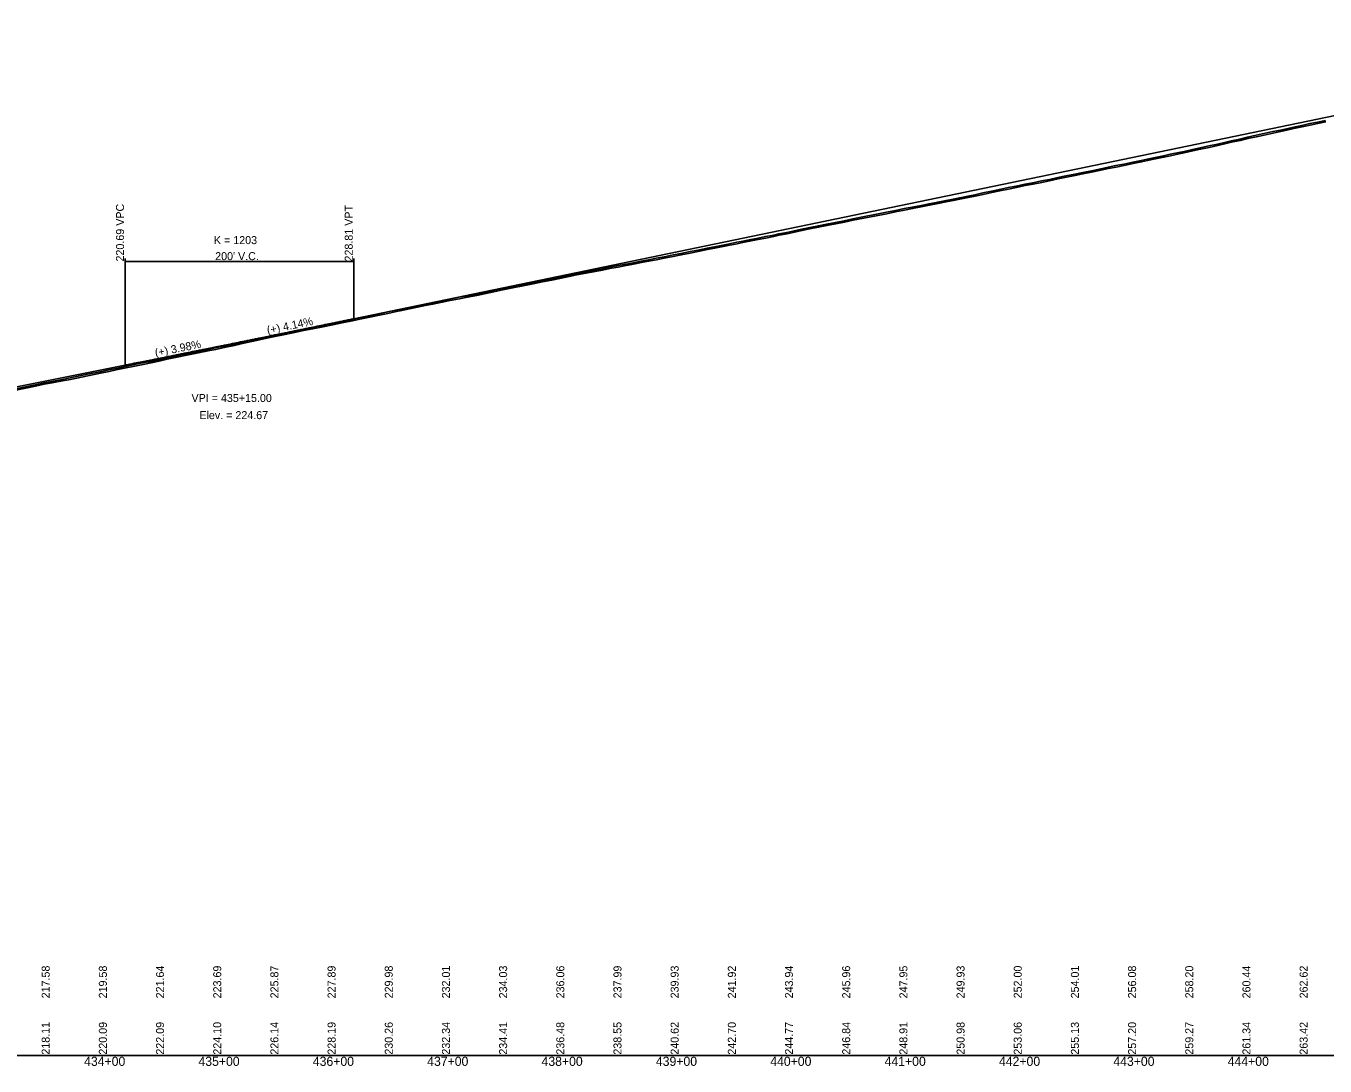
# Model space of a CAD drawing. Extents: x 1876258 to 1932803, y 754739 to 837911.
# Drawn here: x 1921691 to 1922827, y 827954 to 828863 of the extents above; entities that cross this region are included whole.
import ezdxf

# ---------------------------------------------------------------- set-up
doc = ezdxf.new("R2010")
doc.units = 0
for name, color, linetype in [('RD_DDB_GradeTX', 7, 'Continuous'), ('RD_DDB_Profile_EX', 7, 'Continuous'), ('RD_DDB_Profile_Lbl', 7, 'Continuous'), ('RD_DDB_Profile_PR', 7, 'Continuous'), ('RD_DDB_StaTX', 7, 'Continuous'), ('RD_DDB_StripGrade', 7, 'Continuous'), ('RD_DDB_VCLbl', 7, 'Continuous'), ('RD_GPK_Profile_Cell', 7, 'Continuous'), ('RD_Sketch1', 7, 'Continuous')]:
    doc.layers.add(name, color=color, linetype=linetype)

msp = doc.modelspace()

# ---------------------------------------------------------------- linework, layer by layer
at = {"layer": 'RD_DDB_GradeTX'}
for p in [(1921956.4, 828602.4), (1921799.6, 828570.5)]:
    msp.add_line(p, (1921878.1, 828586.1), dxfattribs=at)
at = {"layer": 'RD_DDB_Profile_EX'}
for points in [[(1922741, 828760.1), (1922745.5, 828761.1), (1922753, 828762.7), (1922759.9, 828764.3), (1922767.3, 828766), (1922774.2, 828767.4), (1922782, 828769.1), (1922787.1, 828770.2), (1922793.8, 828771.7), (1922799.9, 828773.1), (1922807.2, 828774.6), (1922814.3, 828776.2), (1922820.9, 828777.6), (1922828, 828779.1)], [(1921993.6, 828608.6), (1922000.5, 828609.9), (1922007.9, 828611.6), (1922015.3, 828613.2), (1922018.5, 828613.8), (1922026.8, 828615.5), (1922033.7, 828616.9), (1922042, 828618.6), (1922047.2, 828619.7), (1922055.4, 828621.3), (1922062.3, 828622.7), (1922070.5, 828624.3), (1922077.4, 828625.7), (1922085.6, 828627.3), (1922092.2, 828628.6), (1922100.4, 828630.3), (1922108.3, 828632), (1922134.8, 828637.4), (1922143, 828639.1), (1922151.2, 828640.7), (1922158.1, 828642.1), (1922166.3, 828643.8), (1922173.2, 828645.2), (1922181.3, 828646.7), (1922187.4, 828647.8), (1922194, 828649.1), (1922198.1, 828649.9), (1922203.4, 828651), (1922209.3, 828652), (1922214.6, 828653), (1922222.5, 828654.5), (1922229.6, 828655.9), (1922237.5, 828657.5), (1922242.6, 828658.5), (1922249.5, 828659.9), (1922257.4, 828661.4), (1922264.4, 828662.7), (1922272.3, 828664.3), (1922279.3, 828665.7), (1922287.2, 828667.3), (1922295.1, 828668.9), (1922305.4, 828670.9), (1922313.3, 828672.4), (1922316.9, 828673.2), (1922324.1, 828674.6), (1922331.7, 828676.1), (1922338.4, 828677.4), (1922345.4, 828678.8), (1922350.1, 828679.8), (1922356.9, 828681.2), (1922362.2, 828682.3), (1922369.9, 828683.9), (1922376.9, 828685.4), (1922384.5, 828686.8), (1922391.8, 828688.3), (1922399.4, 828689.8), (1922407, 828691.4), (1922414.6, 828692.9), (1922444, 828698.7), (1922451.8, 828700.3), (1922459.6, 828701.8), (1922466.6, 828703.2), (1922474.3, 828704.8), (1922481.3, 828706.1), (1922489, 828707.7), (1922496.1, 828709.1), (1922502.5, 828710.3), (1922508.1, 828711.4), (1922513.8, 828712.6), (1922521.3, 828714.1), (1922528.3, 828715.6), (1922536, 828717.2), (1922542.9, 828718.6), (1922550.5, 828720.2), (1922557.4, 828721.7), (1922565, 828723.2), (1922572, 828724.6), (1922579.6, 828726.1), (1922586.5, 828727.5), (1922594.1, 828729.1), (1922601.1, 828730.5), (1922608.7, 828732), (1922615.6, 828733.4), (1922623.2, 828735), (1922630.2, 828736.5), (1922638, 828738.1), (1922644.8, 828739.4), (1922651.7, 828740.9), (1922659.5, 828742.5), (1922666.9, 828744), (1922672.1, 828745.1), (1922679, 828746.6), (1922686.4, 828748.1), (1922692.3, 828749.3), (1922699.8, 828751), (1922704.2, 828751.9), (1922711.7, 828753.5), (1922718.5, 828755), (1922726, 828756.7), (1922733.5, 828758.4), (1922741, 828760.1)], [(1921679.9, 828543.9), (1921699.8, 828548), (1921707.4, 828549.6), (1921714.2, 828550.9), (1921723.2, 828552.6), (1921730.3, 828553.9), (1921740, 828555.9), (1921746.9, 828557.4), (1921756.4, 828559.4), (1921764.1, 828560.9), (1921770.3, 828562.2), (1921793.7, 828567), (1921800.7, 828568.3), (1921807.8, 828569.9), (1921814.9, 828571.4), (1921840.7, 828576.7), (1921847.9, 828578.1), (1921852.1, 828579), (1921857.4, 828580.1), (1921864.7, 828581.6), (1921873.6, 828583.5), (1921882, 828585.4), (1921890.3, 828587.3), (1921899.4, 828589.3), (1921907.6, 828591), (1921916.6, 828592.9), (1921925, 828594.6), (1921934, 828596.5), (1921942.3, 828598.1), (1921951.3, 828599.9), (1921959.6, 828601.5), (1921968, 828603.3), (1921976.9, 828605.1), (1921984.8, 828606.7), (1921993.6, 828608.6)]]:
    msp.add_lwpolyline(points, dxfattribs=at)
at = {"layer": 'RD_DDB_Profile_PR'}
for p, q in [((1921978.1, 828606.9), (1923213.1, 828862.8)), ((1921449.1, 828500.8), (1921778.1, 828566.3))]:
    msp.add_line(p, q, dxfattribs=at)
msp.add_spline([(1921778.1, 828566.3), (1921782.1, 828567.1), (1921786.1, 828567.9), (1921790.1, 828568.7), (1921794.1, 828569.4), (1921798.1, 828570.2), (1921802.1, 828571), (1921806.1, 828571.8), (1921810.1, 828572.6), (1921814.1, 828573.4), (1921818.1, 828574.2), (1921822.1, 828575.1), (1921826.1, 828575.9), (1921830.1, 828576.7), (1921834.1, 828577.5), (1921838.1, 828578.3), (1921842.1, 828579.1), (1921846.1, 828579.9), (1921850.1, 828580.7), (1921854.1, 828581.5), (1921858.1, 828582.3), (1921862.1, 828583.1), (1921866.1, 828583.9), (1921870.1, 828584.7), (1921874.1, 828585.5), (1921878.1, 828586.4), (1921882.1, 828587.2), (1921886.1, 828588), (1921890.1, 828588.8), (1921894.1, 828589.6), (1921898.1, 828590.4), (1921902.1, 828591.2), (1921906.1, 828592.1), (1921910.1, 828592.9), (1921914.1, 828593.7), (1921918.1, 828594.5), (1921922.1, 828595.3), (1921926.1, 828596.2), (1921930.1, 828597), (1921934.1, 828597.8), (1921938.1, 828598.6), (1921942.1, 828599.4), (1921946.1, 828600.3), (1921950.1, 828601.1), (1921954.1, 828601.9), (1921958.1, 828602.7), (1921962.1, 828603.6), (1921966.1, 828604.4), (1921970.1, 828605.2), (1921974.1, 828606), (1921978.1, 828606.9)], degree=3, dxfattribs=at)
at = {"layer": 'RD_DDB_VCLbl'}
for p, q in [((1921778.1, 828659.4), (1921778.1, 828566.3)), ((1921778.1, 828656.9), (1921978.1, 828656.9)), ((1921978.1, 828659.4), (1921978.1, 828606.9))]:
    msp.add_line(p, q, dxfattribs=at)
at = {"layer": 'RD_GPK_Profile_Cell'}
msp.add_line((1878363.1, 827962.8), (1926563.1, 827962.8), dxfattribs=at)
at = {"layer": 'RD_Sketch1'}
msp.add_lwpolyline([(1921679.6, 828545.1), (1921699.5, 828549.2), (1921707.2, 828550.8), (1921714, 828552.1), (1921722.9, 828553.8), (1921730, 828555.2), (1921739.7, 828557.2), (1921746.6, 828558.6), (1921756.2, 828560.6), (1921763.8, 828562.1), (1921770.1, 828563.4), (1921793.4, 828568.2), (1921800.5, 828569.6), (1921807.5, 828571.1), (1921814.6, 828572.6), (1921840.4, 828577.9), (1921847.6, 828579.4), (1921851.9, 828580.3), (1921857.1, 828581.4), (1921864.4, 828582.8), (1921873.3, 828584.7), (1921881.7, 828586.6), (1921890, 828588.5), (1921899.1, 828590.5), (1921907.4, 828592.3), (1921916.4, 828594.1), (1921924.7, 828595.8), (1921933.7, 828597.7), (1921942, 828599.3), (1921951, 828601.1), (1921959.3, 828602.8), (1921967.8, 828604.5), (1921976.6, 828606.3), (1921984.6, 828607.9), (1921993.4, 828609.8), (1922000.2, 828611.2), (1922007.7, 828612.8), (1922015, 828614.4), (1922018.2, 828615), (1922026.6, 828616.7), (1922033.5, 828618.1), (1922041.7, 828619.8), (1922046.9, 828620.9), (1922055.1, 828622.5), (1922062, 828623.9), (1922070.2, 828625.6), (1922077.1, 828626.9), (1922085.3, 828628.5), (1922092, 828629.9), (1922100.1, 828631.5), (1922108.1, 828633.2), (1922134.5, 828638.6), (1922142.8, 828640.3), (1922150.9, 828641.9), (1922157.8, 828643.3), (1922166, 828645), (1922173, 828646.4), (1922181.1, 828648), (1922187.2, 828649.1), (1922193.8, 828650.3), (1922197.9, 828651.1), (1922203.2, 828652.2), (1922209.1, 828653.3), (1922214.4, 828654.3), (1922222.2, 828655.7), (1922229.4, 828657.2), (1922237.3, 828658.8), (1922242.4, 828659.8), (1922249.3, 828661.1), (1922257.2, 828662.6), (1922264.1, 828663.9), (1922272.1, 828665.6), (1922279, 828666.9), (1922286.9, 828668.5), (1922294.9, 828670.1), (1922305.2, 828672.2), (1922313, 828673.7), (1922316.7, 828674.4), (1922323.8, 828675.8), (1922331.5, 828677.4), (1922338.1, 828678.7), (1922345.2, 828680), (1922349.8, 828681), (1922356.6, 828682.4), (1922362, 828683.5), (1922369.6, 828685.2), (1922376.7, 828686.6), (1922384.3, 828688.1), (1922391.5, 828689.5), (1922399.2, 828691.1), (1922406.8, 828692.6), (1922414.4, 828694.1), (1922443.7, 828699.9), (1922451.6, 828701.5), (1922459.4, 828703.1), (1922466.3, 828704.5), (1922474.1, 828706), (1922481.1, 828707.4), (1922488.7, 828708.9), (1922495.9, 828710.3), (1922502.2, 828711.5), (1922507.9, 828712.7), (1922513.5, 828713.8), (1922521, 828715.3), (1922528, 828716.8), (1922535.7, 828718.4), (1922542.6, 828719.9), (1922550.3, 828721.5), (1922557.2, 828722.9), (1922564.8, 828724.4), (1922571.7, 828725.8), (1922579.4, 828727.3), (1922586.3, 828728.7), (1922593.8, 828730.3), (1922600.8, 828731.7), (1922608.4, 828733.2), (1922615.4, 828734.6), (1922623, 828736.2), (1922630, 828737.7), (1922637.7, 828739.3), (1922644.5, 828740.7), (1922651.4, 828742.1), (1922659.2, 828743.7), (1922666.6, 828745.2), (1922671.8, 828746.3), (1922678.8, 828747.8), (1922686.2, 828749.4), (1922692, 828750.6), (1922699.6, 828752.2), (1922704, 828753.1), (1922711.4, 828754.7), (1922718.2, 828756.2), (1922725.7, 828758), (1922733.2, 828759.6), (1922740.7, 828761.3), (1922745.2, 828762.3), (1922752.7, 828763.9), (1922759.6, 828765.5), (1922767.1, 828767.2), (1922773.9, 828768.7), (1922781.8, 828770.4), (1922786.9, 828771.5), (1922793.5, 828772.9), (1922799.6, 828774.3), (1922806.9, 828775.9), (1922814.1, 828777.4), (1922820.7, 828778.8), (1922827.7, 828780.3)], dxfattribs=at)

# ---------------------------------------------------------------- texts
at = {"layer": 'RD_DDB_GradeTX'}
for s, rotation, p in [('(+) 4.14%', 11.7064, (1921902.8, 828593.3)), ('(+) 3.98%', 11.2488, (1921804.8, 828573.6))]:
    msp.add_text(s, height=7, rotation=rotation, dxfattribs=at).set_placement(p)
at = {"layer": 'RD_DDB_Profile_Lbl'}
for s, p in [('VPI = 435+15.00', (1921836.1, 828534.1)), ('Elev. = 224.67', (1921843, 828519.1))]:
    msp.add_text(s, height=7, dxfattribs=at).set_placement(p)
at = {"layer": 'RD_DDB_StaTX'}
for s, p in [('434+00', (1921742.2, 827953.8)), ('435+00', (1921842.2, 827953.8)), ('436+00', (1921942.2, 827953.8)), ('437+00', (1922042.2, 827953.8)), ('438+00', (1922142.2, 827953.8)), ('439+00', (1922242.2, 827953.8)), ('440+00', (1922342.2, 827953.8)), ('441+00', (1922442.2, 827953.8)), ('442+00', (1922542.2, 827953.8)), ('443+00', (1922642.2, 827953.8)), ('444+00', (1922742.2, 827953.8))]:
    msp.add_text(s, height=8, dxfattribs=at).set_placement(p)
at = {"layer": 'RD_DDB_StripGrade'}
for s, p in [('220.69 VPC', (1921777.1, 828656.9)), ('228.81 VPT', (1921977.1, 828656.9)), ('217.58', (1921712.1, 828012.8)), ('219.58', (1921762.1, 828012.8)), ('221.64', (1921812.1, 828012.8)), ('223.69', (1921862.1, 828012.8)), ('225.87', (1921912.1, 828012.8)), ('227.89', (1921962.1, 828012.8)), ('229.98', (1922012.1, 828012.8)), ('232.01', (1922062.1, 828012.8)), ('234.03', (1922112.1, 828012.8)), ('236.06', (1922162.1, 828012.8)), ('237.99', (1922212.1, 828012.8)), ('239.93', (1922262.1, 828012.8)), ('241.92', (1922312.1, 828012.8)), ('243.94', (1922362.1, 828012.8)), ('245.96', (1922412.1, 828012.8)), ('247.95', (1922462.1, 828012.8)), ('249.93', (1922512.1, 828012.8)), ('252.00', (1922562.1, 828012.8)), ('254.01', (1922612.1, 828012.8)), ('256.08', (1922662.1, 828012.8)), ('258.20', (1922712.1, 828012.8)), ('260.44', (1922762.1, 828012.8)), ('262.62', (1922812.1, 828012.8)), ('218.11', (1921712.1, 827963.6)), ('220.09', (1921762.1, 827963.6)), ('222.09', (1921812.1, 827963.6)), ('224.10', (1921862.1, 827963.6)), ('226.14', (1921912.1, 827963.6)), ('228.19', (1921962.1, 827963.6)), ('230.26', (1922012.1, 827963.6)), ('232.34', (1922062.1, 827963.6)), ('234.41', (1922112.1, 827963.6)), ('236.48', (1922162.1, 827963.6)), ('238.55', (1922212.1, 827963.6)), ('240.62', (1922262.1, 827963.6)), ('242.70', (1922312.1, 827963.6)), ('244.77', (1922362.1, 827963.6)), ('246.84', (1922412.1, 827963.6)), ('248.91', (1922462.1, 827963.6)), ('250.98', (1922512.1, 827963.6)), ('253.06', (1922562.1, 827963.6)), ('255.13', (1922612.1, 827963.6)), ('257.20', (1922662.1, 827963.6)), ('259.27', (1922712.1, 827963.6)), ('261.34', (1922762.1, 827963.6)), ('263.42', (1922812.1, 827963.6))]:
    msp.add_text(s, height=7, rotation=90, dxfattribs=at).set_placement(p)
at = {"layer": 'RD_DDB_VCLbl'}
for s, p in [('K = 1203', (1921855.7, 828672.1)), ("200' V.C.", (1921856.8, 828658.1))]:
    msp.add_text(s, height=7, dxfattribs=at).set_placement(p)

doc.saveas('drawing.dxf')
